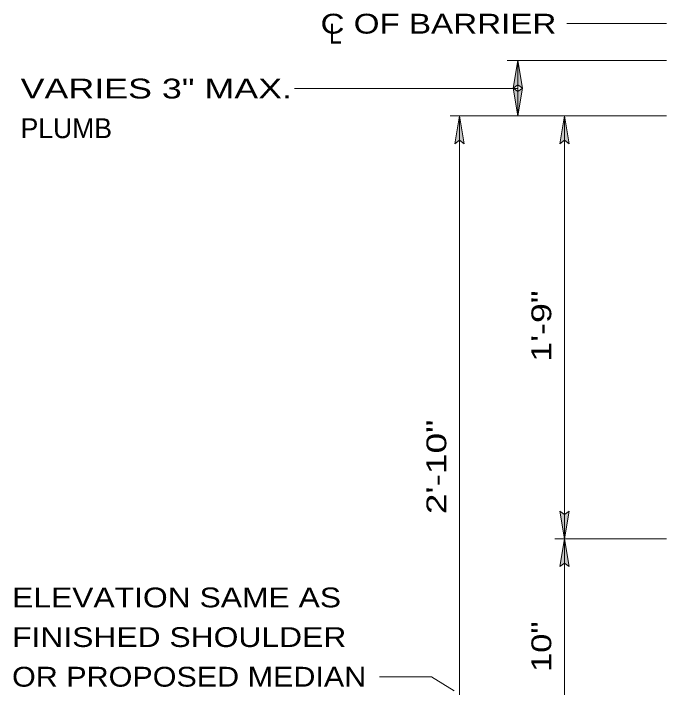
# Model space of a CAD drawing. Extents: x -9.07 to -2.08, y 8.04 to 17.77.
# Drawn here: x -8.806 to -6.83, y 14.699 to 16.739 of the extents above; entities that cross this region are included whole.
import ezdxf
from ezdxf.enums import TextEntityAlignment as Align

# ---------------------------------------------------------------- set-up
doc = ezdxf.new("R2010")
doc.units = 0
doc.header["$LTSCALE"] = 0.024
doc.layers.add('10', color=7, linetype='Continuous', lineweight=13)
doc.layers.add('12', color=7, linetype='Continuous', lineweight=53)

msp = doc.modelspace()

# ---------------------------------------------------------------- hatches: boundary and pattern name
at = {"layer": '10'}
for points in [[(-7.28, 16.59717), (-7.266, 16.51317), (-7.28, 16.52367), (-7.294, 16.51317)], [(-7.28, 16.50283), (-7.266, 16.51333), (-7.28, 16.42933), (-7.294, 16.51333)], [(-7.456, 16.42933), (-7.442, 16.34533), (-7.456, 16.35583), (-7.47, 16.34533)], [(-7.1385, 16.42933), (-7.1245, 16.34533), (-7.1385, 16.35583), (-7.1525, 16.34533)], [(-7.1385, 15.14883), (-7.1245, 15.23283), (-7.1385, 15.22233), (-7.1525, 15.23283)], [(-7.1385, 15.14883), (-7.1245, 15.06483), (-7.1385, 15.07533), (-7.1525, 15.06483)]]:
    msp.add_hatch(color=256, dxfattribs=at).paths.add_polyline_path(points)

# ---------------------------------------------------------------- linework, layer by layer
for p, q in [((-7.13167, 16.70867), (-6.82983, 16.70867)), ((-6.82983, 16.59717), (-7.31167, 16.59717)), ((-7.294, 16.51317), (-7.28, 16.59717)), ((-7.28, 16.42933), (-7.28, 16.59717)), ((-7.266, 16.51317), (-7.28, 16.59717)), ((-7.9555, 16.51217), (-7.28, 16.51217)), ((-7.294, 16.51317), (-7.28, 16.52367)), ((-7.294, 16.51333), (-7.28, 16.42933)), ((-7.294, 16.51333), (-7.28, 16.50283)), ((-7.266, 16.51317), (-7.28, 16.52367)), ((-7.266, 16.51333), (-7.28, 16.42933)), ((-7.266, 16.51333), (-7.28, 16.50283)), ((-6.82983, 16.42933), (-7.48483, 16.42933)), ((-7.47, 16.34533), (-7.456, 16.42933)), ((-7.442, 16.34533), (-7.456, 16.42933)), ((-7.456, 14.29567), (-7.456, 16.42933)), ((-7.1525, 16.34533), (-7.1385, 16.42933)), ((-7.1245, 16.34533), (-7.1385, 16.42933)), ((-7.1385, 15.14883), (-7.1385, 16.42933)), ((-7.47, 16.34533), (-7.456, 16.35583)), ((-7.442, 16.34533), (-7.456, 16.35583)), ((-7.1525, 16.34533), (-7.1385, 16.35583)), ((-7.1245, 16.34533), (-7.1385, 16.35583)), ((-7.1525, 15.23283), (-7.1385, 15.14883)), ((-7.1525, 15.23283), (-7.1385, 15.22233)), ((-7.1245, 15.23283), (-7.1385, 15.14883)), ((-7.1245, 15.23283), (-7.1385, 15.22233)), ((-7.16733, 15.14883), (-6.82983, 15.14883)), ((-7.1525, 15.06483), (-7.1385, 15.14883)), ((-7.1245, 15.06483), (-7.1385, 15.14883)), ((-7.1385, 14.48783), (-7.1385, 15.14883)), ((-7.1525, 15.06483), (-7.1385, 15.07533)), ((-7.1245, 15.06483), (-7.1385, 15.07533)), ((-7.69817, 14.73167), (-7.54067, 14.73167)), ((-7.47233, 14.68867), (-7.54067, 14.73167))]:
    msp.add_line(p, q, dxfattribs=at)
for points in [[(-7.28, 16.59717), (-7.266, 16.51317), (-7.28, 16.52367), (-7.294, 16.51317)], [(-7.28, 16.50283), (-7.266, 16.51333), (-7.28, 16.42933), (-7.294, 16.51333)], [(-7.456, 16.42933), (-7.442, 16.34533), (-7.456, 16.35583), (-7.47, 16.34533)], [(-7.1385, 16.42933), (-7.1245, 16.34533), (-7.1385, 16.35583), (-7.1525, 16.34533)], [(-7.1385, 15.14883), (-7.1245, 15.23283), (-7.1385, 15.22233), (-7.1525, 15.23283)], [(-7.1385, 15.14883), (-7.1245, 15.06483), (-7.1385, 15.07533), (-7.1525, 15.06483)]]:
    msp.add_lwpolyline(points, close=True, dxfattribs=at)

# ---------------------------------------------------------------- texts
at = {"layer": '12'}
for s, width, p in [('C OF BARRIER', 1.25, (-7.16317, 16.67858)), ('L', 0.85, (-7.81242, 16.6485))]:
    msp.add_text(s, height=0.06001, dxfattribs=dict(at, width=width)).set_placement(p, align=Align.RIGHT)
for s, width, p in [('VARIES 3" MAX.', 1.35, (-8.784, 16.48217)), ('ELEVATION SAME AS', 1.2, (-8.80992, 14.94158)), ('FINISHED SHOULDER', 1.2, (-8.80992, 14.82158)), ('OR PROPOSED MEDIAN', 1.15, (-8.80992, 14.70158))]:
    msp.add_text(s, height=0.06001, dxfattribs=dict(at, width=width)).set_placement(p)
msp.add_text('PLUMB', height=0.06001, dxfattribs=at).set_placement((-8.784, 16.36217))
for s, width, p in [('1\'-9"', 1.35, (-7.1785, 15.79325)), ('2\'-10"', 1.4, (-7.49608, 15.36675)), ('10"', 1.3, (-7.1785, 14.82258))]:
    msp.add_text(s, height=0.06001, rotation=90, dxfattribs=dict(at, width=width)).set_placement(p, align=Align.CENTER)

doc.saveas('drawing.dxf')
